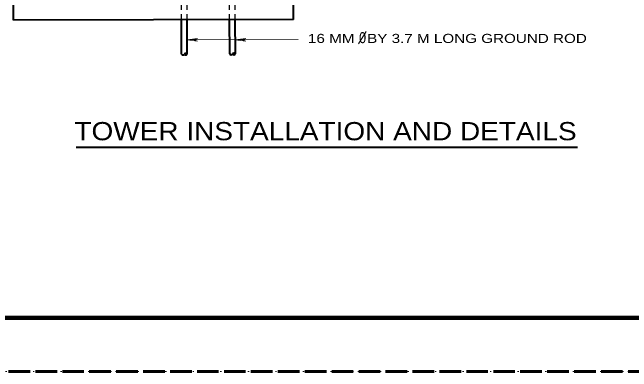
# Model space of a CAD drawing. Extents: x 312583 to 312854, y 144419 to 144597.
# Drawn here: x 312751.3 to 312803, y 144418.6 to 144448.6 of the extents above; entities that cross this region are included whole.
import ezdxf
from ezdxf.enums import TextEntityAlignment as Align

# ---------------------------------------------------------------- set-up
doc = ezdxf.new("R2010")
doc.units = 0
doc.header["$LTSCALE"] = 0.3
for name, pattern in [('DOTTED', [1.5, 0.3, -1.2]), ('LONG_DASHED', [7.5, 6, -1.5]), ('SHORT_DASHED', [2.7, 1.5, -1.2])]:
    doc.linetypes.add(name, pattern=pattern)
for name, color, linetype, lineweight in [('1', 7, 'Continuous', 40), ('2', 7, 'Continuous', 13), ('62', 7, 'DOTTED', 13), ('63', 7, 'LONG_DASHED', 60)]:
    doc.layers.add(name, color=color, linetype=linetype, lineweight=lineweight)

msp = doc.modelspace()

# ---------------------------------------------------------------- linework, layer by layer
at = {"layer": '1'}
for p, q in [((312751.3725, 144447.9456), (312751.3572, 144453.5422)), ((312774.7558, 144447.9992), (312774.7405, 144453.5959)), ((312774.7558, 144447.9992), (312751.3725, 144447.9456)), ((312765.4025, 144445.0936), (312765.3948, 144447.9762)), ((312765.8778, 144445.0936), (312765.8702, 144447.9762)), ((312769.4275, 144445.1089), (312769.4198, 144447.9916)), ((312769.9028, 144445.1089), (312769.8952, 144447.9916))]:
    msp.add_line(p, q, dxfattribs=at)
at = {"layer": '1', "linetype": 'SHORT_DASHED', "lineweight": 25}
for p, q in [((312765.3948, 144447.9762), (312765.3872, 144452.5839)), ((312769.4198, 144447.9916), (312769.4122, 144452.5992))]:
    msp.add_line(p, q, dxfattribs=at)
at = {"layer": '1', "lineweight": 158}
msp.add_line((312616.5, 144423.0846), (312849, 144423.0846), dxfattribs=at)
at = {"layer": '1', "linetype": 'SHORT_DASHED', "lineweight": 25}
for points in [[(312765.8702, 144447.9762), (312765.8625, 144452.5839), (312765.3872, 144452.5839)], [(312769.8952, 144447.9916), (312769.8875, 144452.5992), (312769.4122, 144452.5992)]]:
    msp.add_lwpolyline(points, dxfattribs=at)
at = {"layer": '1'}
for centre, start, end in [((312765.5213, 144445.1613), 209.67849, 330.32151), ((312765.759, 144445.0258), 29.67849, 150.32151), ((312765.759, 144445.1613), 209.67849, 330.32151), ((312769.5463, 144445.1766), 209.67849, 330.32151), ((312769.784, 144445.0412), 29.67849, 150.32151), ((312769.784, 144445.1766), 209.67849, 330.32151)]:
    msp.add_arc(centre, 0.1368, start, end, dxfattribs=at)
at = {"layer": '2'}
for p, q in [((312780.1918, 144445.9557), (312780.8281, 144446.9754)), ((312765.8702, 144446.2896), (312766.7365, 144446.3969)), ((312766.7365, 144446.3969), (312766.4605, 144446.2896)), ((312769.8952, 144446.2972), (312770.7615, 144446.4046)), ((312770.7615, 144446.4046), (312770.4855, 144446.2972)), ((312765.8702, 144446.2896), (312775.1468, 144446.3049)), ((312765.8702, 144446.2896), (312766.7365, 144446.1822)), ((312766.7365, 144446.1822), (312766.4605, 144446.2896)), ((312769.8952, 144446.2972), (312770.7615, 144446.1899)), ((312770.7615, 144446.1899), (312770.4855, 144446.2972))]:
    msp.add_line(p, q, dxfattribs=at)
at = {"layer": '2', "lineweight": 40}
msp.add_line((312756.5938, 144437.3312), (312798.4913, 144437.3312), dxfattribs=at)
at = {"layer": '62'}
msp.add_lwpolyline([(312601.2, 144418.5846), (312853.5, 144418.5846), (312853.5, 144596.7846)], dxfattribs=at)
at = {"layer": '63'}
msp.add_line((312851.75, 144418.5846), (312583.526, 144418.5846), dxfattribs=at)

# ---------------------------------------------------------------- texts
at = {"layer": '2'}
for s, height, width, p in [('0', 0.92, 0.85, (312780.5291, 144446.0094)), ('TOWER INSTALLATION AND DETAILS', 1.52, 1.15, (312777.4297, 144437.9046))]:
    msp.add_text(s, height=height, dxfattribs=dict(at, width=width)).set_placement(p, align=Align.CENTER)
at = {"layer": '2', "width": 1.25}
msp.add_text('16 MM   BY 3.7 M LONG GROUND ROD', height=0.76, dxfattribs=at).set_placement((312775.9638, 144446.0279))

doc.saveas('drawing.dxf')
